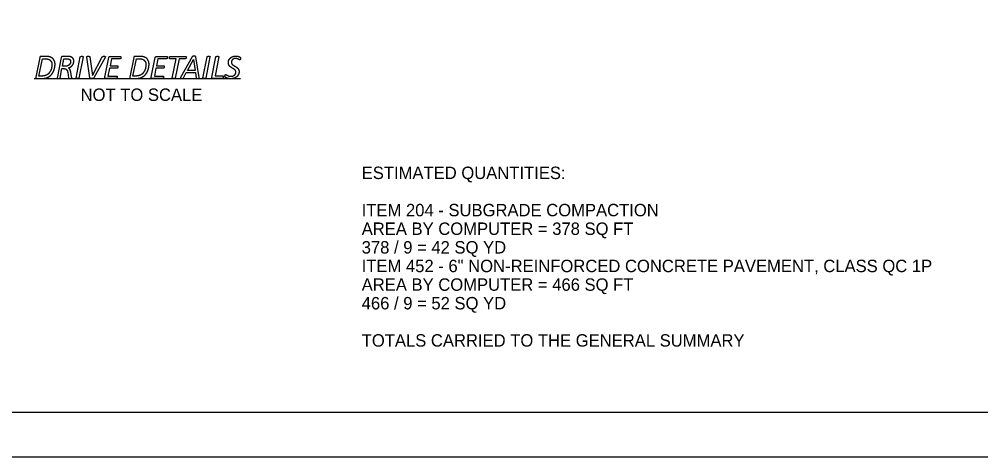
# Model space of a CAD drawing. Extents: x 0 to 3518, y -260 to 220.
# Drawn here: x 60.2 to 168.6, y -220 to -170.7 of the extents above; entities that cross this region are included whole.
import ezdxf

# ---------------------------------------------------------------- set-up
doc = ezdxf.new("R2010")
doc.units = 0
for name, color, linetype in [('DR_X_Culvert', 7, 'Continuous'), ('PF_X_Ground_Line', 7, 'Continuous'), ('SC_Scratch1', 7, 'Continuous'), ('TX_P_1', 7, 'Continuous')]:
    doc.layers.add(name, color=color, linetype=linetype)

msp = doc.modelspace()

# ---------------------------------------------------------------- linework, layer by layer
at = {"layer": 'DR_X_Culvert'}
for p, q in [((62.52, -174.98), (62.08, -177.2)), ((63.21, -174.85), (62.68, -174.85)), ((64.94, -174.98), (64.48, -177.29)), ((65.65, -174.85), (65.11, -174.85)), ((66.01, -175.42), (66.01, -175.42)), ((66.36, -175.37), (66.36, -175.37)), ((66.62, -177.29), (67.1, -174.9)), ((67.43, -174.9), (66.95, -177.29)), ((68.18, -177.28), (67.83, -174.95)), ((69.9, -174.97), (68.62, -177.28)), ((69.86, -177.2), (70.31, -174.98)), ((70.46, -174.85), (71.64, -174.85)), ((71.68, -174.91), (71.68, -174.91)), ((73.12, -174.98), (72.68, -177.2)), ((73.81, -174.85), (73.28, -174.85)), ((75.1, -177.2), (75.54, -174.98)), ((75.69, -174.85), (76.87, -174.85)), ((76.92, -174.91), (76.92, -174.91)), ((77.26, -174.85), (78.99, -174.85)), ((79.7, -174.91), (78.4, -177.22)), ((79.04, -174.92), (79.04, -174.92)), ((80.51, -177.22), (80.14, -174.91)), ((80.91, -177.29), (81.39, -174.9)), ((81.72, -174.9), (81.24, -177.29)), ((81.92, -177.2), (82.38, -174.9)), ((85.17, -175.03), (85.17, -175.03)), ((63.9, -175.77), (63.9, -175.77)), ((64.25, -175.74), (64.25, -175.74)), ((65.68, -176.68), (65.78, -177.27)), ((66.12, -177.16), (66.02, -176.61)), ((74.5, -175.77), (74.5, -175.77)), ((74.85, -175.74), (74.85, -175.74)), ((61.9, -177.34), (85.17, -177.34)), ((62.18, -177.34), (62.73, -177.34)), ((71.15, -177.34), (69.96, -177.34)), ((72.78, -177.34), (73.33, -177.34)), ((76.39, -177.34), (75.19, -177.34)), ((83.12, -177.34), (82.02, -177.34)), ((83.22, -177.12), (83.22, -177.12))]:
    msp.add_line(p, q, dxfattribs=at)
for points in [[(62.78, -177.06), (62.43, -177.06), (62.82, -175.12), (63.17, -175.12)], [(65.37, -175.96), (65.08, -175.96), (65.25, -175.12), (65.59, -175.12)], [(68.17, -174.9), (68.46, -177), (68.46, -177), (69.57, -174.9)], [(71.58, -175.12), (70.61, -175.12), (70.45, -175.9), (71.29, -175.9)], [(73.38, -177.06), (73.03, -177.06), (73.42, -175.12), (73.77, -175.12)], [(76.82, -175.12), (75.85, -175.12), (75.69, -175.9), (76.53, -175.9)], [(77.47, -177.29), (77.9, -175.13), (77.2, -175.13)], [(78.93, -175.13), (78.23, -175.13), (77.8, -177.29)], [(82.71, -174.9), (82.29, -177.05), (83.18, -177.05)], [(64.81, -177.29), (65.03, -176.23), (65.25, -176.23)], [(71.24, -176.17), (70.4, -176.17), (70.22, -177.06), (71.21, -177.06)], [(76.47, -176.17), (75.63, -176.17), (75.46, -177.06), (76.45, -177.06)], [(78.73, -177.28), (79.05, -176.68), (80.09, -176.68), (80.18, -177.29)]]:
    msp.add_lwpolyline(points, dxfattribs=at)
msp.add_lwpolyline([(79.86, -175.18), (80.05, -176.42), (79.19, -176.42), (79.86, -175.18)], close=True, dxfattribs=at)
for points in [[(62.58, -174.88), (62.53, -174.91), (62.52, -174.98)], [(62.68, -174.85), (62.62, -174.85), (62.58, -174.88)], [(63.17, -175.12), (63.38, -175.12), (63.52, -175.17)], [(63.68, -174.91), (63.49, -174.85), (63.21, -174.85)], [(63.52, -175.17), (63.65, -175.22), (63.73, -175.31)], [(63.99, -175.08), (63.87, -174.97), (63.68, -174.91)], [(63.73, -175.31), (63.82, -175.39), (63.86, -175.51)], [(63.86, -175.51), (63.9, -175.63), (63.9, -175.77)], [(64.18, -175.37), (64.12, -175.2), (63.99, -175.08)], [(64.25, -175.74), (64.25, -175.53), (64.18, -175.37)], [(65.01, -174.88), (64.96, -174.91), (64.94, -174.98)], [(65.11, -174.85), (65.05, -174.85), (65.01, -174.88)], [(65.59, -175.12), (65.7, -175.12), (65.78, -175.14)], [(65.96, -174.88), (65.82, -174.85), (65.65, -174.85)], [(65.78, -175.14), (65.86, -175.16), (65.91, -175.2)], [(65.97, -175.62), (65.93, -175.71), (65.86, -175.79)], [(65.91, -175.2), (65.96, -175.24), (65.98, -175.3)], [(66.18, -174.98), (66.09, -174.92), (65.96, -174.88)], [(66.01, -175.42), (66.01, -175.52), (65.97, -175.62)], [(65.98, -175.3), (66.01, -175.35), (66.01, -175.42)], [(66.32, -175.15), (66.27, -175.05), (66.18, -174.98)], [(66.21, -175.84), (66.29, -175.74), (66.33, -175.62)], [(66.36, -175.37), (66.36, -175.24), (66.32, -175.15)], [(66.33, -175.62), (66.36, -175.5), (66.36, -175.37)], [(67.1, -174.9), (67.1, -174.88), (67.11, -174.87)], [(67.11, -174.87), (67.12, -174.86), (67.15, -174.85)], [(67.15, -174.85), (67.17, -174.85), (67.2, -174.84)], [(67.2, -174.84), (67.23, -174.84), (67.28, -174.84)], [(67.28, -174.84), (67.32, -174.84), (67.35, -174.84)], [(67.35, -174.84), (67.38, -174.85), (67.4, -174.85)], [(67.4, -174.85), (67.42, -174.86), (67.43, -174.87)], [(67.43, -174.87), (67.43, -174.88), (67.43, -174.9)], [(67.82, -174.89), (67.83, -174.87), (67.84, -174.86)], [(67.83, -174.95), (67.82, -174.91), (67.82, -174.89)], [(67.84, -174.86), (67.86, -174.84), (67.89, -174.84)], [(67.89, -174.84), (67.93, -174.84), (67.98, -174.84)], [(67.98, -174.84), (68.04, -174.84), (68.08, -174.84)], [(68.08, -174.84), (68.11, -174.84), (68.13, -174.85)], [(68.13, -174.85), (68.15, -174.86), (68.16, -174.87)], [(68.16, -174.87), (68.16, -174.88), (68.17, -174.9)], [(69.57, -174.9), (69.58, -174.88), (69.59, -174.87)], [(69.59, -174.87), (69.6, -174.86), (69.62, -174.85)], [(69.62, -174.85), (69.65, -174.84), (69.68, -174.84)], [(69.68, -174.84), (69.72, -174.84), (69.77, -174.84)], [(69.77, -174.84), (69.83, -174.84), (69.87, -174.84)], [(69.87, -174.84), (69.9, -174.85), (69.92, -174.86)], [(69.92, -174.9), (69.92, -174.92), (69.9, -174.97)], [(69.92, -174.86), (69.93, -174.87), (69.92, -174.9)], [(70.31, -174.98), (70.32, -174.91), (70.37, -174.88)], [(70.37, -174.88), (70.42, -174.85), (70.46, -174.85)], [(71.62, -175.11), (71.6, -175.12), (71.58, -175.12)], [(71.65, -175.08), (71.63, -175.1), (71.62, -175.11)], [(71.64, -174.85), (71.68, -174.85), (71.68, -174.91)], [(71.66, -175.03), (71.66, -175.06), (71.65, -175.08)], [(71.68, -174.98), (71.67, -175.01), (71.66, -175.03)], [(71.68, -174.91), (71.68, -174.92), (71.68, -174.94)], [(71.68, -174.94), (71.68, -174.96), (71.68, -174.98)], [(73.18, -174.88), (73.13, -174.91), (73.12, -174.98)], [(73.28, -174.85), (73.22, -174.85), (73.18, -174.88)], [(73.77, -175.12), (73.98, -175.12), (74.12, -175.17)], [(74.28, -174.91), (74.09, -174.85), (73.81, -174.85)], [(74.12, -175.17), (74.25, -175.22), (74.33, -175.31)], [(74.6, -175.08), (74.47, -174.97), (74.28, -174.91)], [(74.33, -175.31), (74.42, -175.39), (74.46, -175.51)], [(74.46, -175.51), (74.5, -175.63), (74.5, -175.77)], [(74.78, -175.37), (74.72, -175.2), (74.6, -175.08)], [(74.85, -175.74), (74.85, -175.53), (74.78, -175.37)], [(75.54, -174.98), (75.56, -174.91), (75.6, -174.88)], [(75.6, -174.88), (75.65, -174.85), (75.69, -174.85)], [(76.85, -175.11), (76.84, -175.12), (76.82, -175.12)], [(76.88, -175.08), (76.87, -175.1), (76.85, -175.11)], [(76.87, -174.85), (76.92, -174.85), (76.92, -174.91)], [(76.9, -175.03), (76.89, -175.06), (76.88, -175.08)], [(76.91, -174.98), (76.9, -175.01), (76.9, -175.03)], [(76.92, -174.94), (76.91, -174.96), (76.91, -174.98)], [(76.92, -174.91), (76.92, -174.92), (76.92, -174.94)], [(77.16, -175.03), (77.16, -175.01), (77.17, -174.99)], [(77.16, -175.06), (77.16, -175.05), (77.16, -175.03)], [(77.17, -175.11), (77.16, -175.1), (77.16, -175.06)], [(77.17, -174.99), (77.17, -174.96), (77.18, -174.94)], [(77.2, -175.13), (77.18, -175.13), (77.17, -175.11)], [(77.18, -174.94), (77.19, -174.91), (77.2, -174.89)], [(77.2, -174.89), (77.21, -174.87), (77.23, -174.86)], [(77.23, -174.86), (77.24, -174.85), (77.26, -174.85)], [(78.97, -175.12), (78.95, -175.13), (78.93, -175.13)], [(79, -175.09), (78.99, -175.1), (78.97, -175.12)], [(78.99, -174.85), (79.02, -174.85), (79.03, -174.87)], [(79.02, -175.04), (79.01, -175.07), (79, -175.09)], [(79.03, -174.99), (79.02, -175.01), (79.02, -175.04)], [(79.03, -174.87), (79.04, -174.88), (79.04, -174.92)], [(79.04, -174.92), (79.04, -174.93), (79.03, -174.95)], [(79.03, -174.95), (79.03, -174.97), (79.03, -174.99)], [(79.73, -174.87), (79.71, -174.88), (79.7, -174.91)], [(79.77, -174.85), (79.74, -174.86), (79.73, -174.87)], [(79.83, -174.84), (79.79, -174.84), (79.77, -174.85)], [(79.92, -174.84), (79.87, -174.84), (79.83, -174.84)], [(80.03, -174.84), (79.99, -174.84), (79.92, -174.84)], [(80.09, -174.85), (80.07, -174.84), (80.03, -174.84)], [(80.12, -174.87), (80.12, -174.86), (80.09, -174.85)], [(80.14, -174.91), (80.13, -174.89), (80.12, -174.87)], [(81.39, -174.9), (81.39, -174.88), (81.41, -174.87)], [(81.41, -174.87), (81.42, -174.86), (81.44, -174.85)], [(81.44, -174.85), (81.46, -174.85), (81.49, -174.84)], [(81.49, -174.84), (81.52, -174.84), (81.57, -174.84)], [(81.57, -174.84), (81.62, -174.84), (81.65, -174.84)], [(81.65, -174.84), (81.68, -174.85), (81.7, -174.85)], [(81.7, -174.85), (81.71, -174.86), (81.72, -174.87)], [(81.72, -174.87), (81.73, -174.88), (81.72, -174.9)], [(82.38, -174.9), (82.39, -174.88), (82.4, -174.87)], [(82.4, -174.87), (82.41, -174.86), (82.43, -174.85)], [(82.43, -174.85), (82.45, -174.85), (82.48, -174.84)], [(82.48, -174.84), (82.52, -174.84), (82.56, -174.84)], [(82.56, -174.84), (82.61, -174.84), (82.64, -174.84)], [(82.64, -174.84), (82.67, -174.85), (82.69, -174.85)], [(82.69, -174.85), (82.71, -174.86), (82.71, -174.87)], [(82.71, -174.87), (82.72, -174.88), (82.71, -174.9)], [(83.79, -175.54), (83.79, -175.39), (83.85, -175.26)], [(83.82, -175.76), (83.79, -175.67), (83.79, -175.54)], [(83.85, -175.26), (83.91, -175.13), (84.02, -175.03)], [(84.02, -175.03), (84.13, -174.93), (84.28, -174.87)], [(84.16, -175.36), (84.13, -175.43), (84.13, -175.52)], [(84.13, -175.52), (84.13, -175.6), (84.17, -175.66)], [(84.25, -175.22), (84.19, -175.28), (84.16, -175.36)], [(84.4, -175.12), (84.31, -175.16), (84.25, -175.22)], [(84.28, -174.87), (84.44, -174.81), (84.63, -174.81)], [(84.6, -175.09), (84.49, -175.09), (84.4, -175.12)], [(84.79, -175.11), (84.71, -175.09), (84.6, -175.09)], [(84.63, -174.81), (84.72, -174.81), (84.81, -174.83)], [(84.93, -175.16), (84.87, -175.14), (84.79, -175.11)], [(84.81, -174.83), (84.89, -174.84), (84.96, -174.86)], [(85.03, -175.22), (84.99, -175.19), (84.93, -175.16)], [(84.96, -174.86), (85.02, -174.88), (85.07, -174.91)], [(85.09, -175.24), (85.06, -175.24), (85.03, -175.22)], [(85.07, -174.91), (85.12, -174.94), (85.14, -174.95)], [(85.11, -175.23), (85.1, -175.24), (85.09, -175.24)], [(85.13, -175.2), (85.12, -175.22), (85.11, -175.23)], [(85.15, -175.16), (85.14, -175.18), (85.13, -175.2)], [(85.14, -174.95), (85.15, -174.97), (85.16, -174.99)], [(85.16, -175.11), (85.16, -175.13), (85.15, -175.16)], [(85.16, -174.99), (85.17, -175.01), (85.17, -175.03)], [(85.17, -175.07), (85.17, -175.09), (85.16, -175.11)], [(85.17, -175.03), (85.17, -175.05), (85.17, -175.07)], [(63.65, -176.62), (63.57, -176.75), (63.45, -176.85)], [(63.79, -176.35), (63.74, -176.49), (63.65, -176.62)], [(63.87, -176.06), (63.85, -176.21), (63.79, -176.35)], [(63.9, -175.77), (63.9, -175.91), (63.87, -176.06)], [(63.93, -176.79), (64.02, -176.67), (64.08, -176.54)], [(64.08, -176.54), (64.14, -176.41), (64.17, -176.28)], [(64.17, -176.28), (64.21, -176.14), (64.23, -176)], [(64.23, -176), (64.25, -175.87), (64.25, -175.74)], [(65.25, -176.23), (65.36, -176.23), (65.44, -176.26)], [(65.66, -175.91), (65.54, -175.96), (65.37, -175.96)], [(65.44, -176.26), (65.51, -176.29), (65.56, -176.35)], [(65.56, -176.35), (65.61, -176.41), (65.64, -176.5)], [(65.64, -176.5), (65.67, -176.58), (65.68, -176.68)], [(65.86, -175.79), (65.78, -175.87), (65.66, -175.91)], [(65.76, -176.14), (65.91, -176.1), (66.02, -176.02)], [(65.92, -176.3), (65.86, -176.18), (65.76, -176.14)], [(66.02, -176.61), (65.98, -176.41), (65.92, -176.3)], [(66.02, -176.02), (66.14, -175.94), (66.21, -175.84)], [(71.27, -176.16), (71.26, -176.17), (71.24, -176.17)], [(71.3, -176.13), (71.29, -176.15), (71.27, -176.16)], [(71.29, -175.9), (71.31, -175.9), (71.33, -175.92)], [(71.32, -176.09), (71.31, -176.11), (71.3, -176.13)], [(71.33, -176.04), (71.32, -176.06), (71.32, -176.09)], [(71.33, -175.92), (71.34, -175.94), (71.34, -175.97)], [(71.34, -175.97), (71.34, -175.98), (71.33, -176)], [(71.33, -176), (71.33, -176.02), (71.33, -176.04)], [(74.25, -176.62), (74.17, -176.75), (74.05, -176.85)], [(74.39, -176.35), (74.34, -176.49), (74.25, -176.62)], [(74.47, -176.06), (74.45, -176.21), (74.39, -176.35)], [(74.5, -175.77), (74.5, -175.91), (74.47, -176.06)], [(74.53, -176.79), (74.62, -176.67), (74.68, -176.54)], [(74.68, -176.54), (74.74, -176.41), (74.77, -176.28)], [(74.77, -176.28), (74.81, -176.14), (74.83, -176)], [(74.83, -176), (74.85, -175.87), (74.85, -175.74)], [(76.51, -176.16), (76.49, -176.17), (76.47, -176.17)], [(76.53, -176.13), (76.52, -176.15), (76.51, -176.16)], [(76.53, -175.9), (76.55, -175.9), (76.56, -175.92)], [(76.55, -176.09), (76.54, -176.11), (76.53, -176.13)], [(76.56, -176.04), (76.56, -176.06), (76.55, -176.09)], [(76.56, -175.92), (76.57, -175.94), (76.57, -175.97)], [(76.57, -176), (76.57, -176.02), (76.56, -176.04)], [(76.57, -175.97), (76.57, -175.98), (76.57, -176)], [(83.92, -175.93), (83.86, -175.86), (83.82, -175.76)], [(84.06, -176.05), (83.98, -176), (83.92, -175.93)], [(84.21, -176.16), (84.13, -176.11), (84.06, -176.05)], [(84.17, -175.66), (84.21, -175.73), (84.27, -175.78)], [(84.37, -176.25), (84.29, -176.21), (84.21, -176.16)], [(84.27, -175.78), (84.33, -175.83), (84.4, -175.88)], [(84.51, -176.35), (84.45, -176.29), (84.37, -176.25)], [(84.4, -175.88), (84.48, -175.92), (84.56, -175.97)], [(84.61, -176.46), (84.57, -176.4), (84.51, -176.35)], [(84.56, -175.97), (84.64, -176.02), (84.72, -176.08)], [(84.6, -176.8), (84.64, -176.71), (84.64, -176.61)], [(84.64, -176.61), (84.64, -176.53), (84.61, -176.46)], [(84.72, -176.08), (84.8, -176.13), (84.86, -176.2)], [(84.86, -176.2), (84.92, -176.28), (84.96, -176.37)], [(85, -176.58), (85, -176.75), (84.93, -176.89)], [(84.96, -176.37), (85, -176.46), (85, -176.58)], [(62.08, -177.2), (62.07, -177.24), (62.07, -177.27)], [(62.07, -177.27), (62.08, -177.29), (62.09, -177.31)], [(62.09, -177.31), (62.11, -177.32), (62.13, -177.33)], [(62.13, -177.33), (62.15, -177.34), (62.18, -177.34)], [(62.73, -177.34), (62.98, -177.34), (63.16, -177.3)], [(63.17, -177), (63.01, -177.06), (62.78, -177.06)], [(63.16, -177.3), (63.33, -177.26), (63.48, -177.18)], [(63.45, -176.85), (63.33, -176.95), (63.17, -177)], [(63.48, -177.18), (63.62, -177.11), (63.73, -177.01)], [(63.73, -177.01), (63.85, -176.91), (63.93, -176.79)], [(64.48, -177.29), (64.48, -177.3), (64.49, -177.32)], [(64.49, -177.32), (64.49, -177.33), (64.51, -177.33)], [(64.51, -177.33), (64.53, -177.34), (64.56, -177.34)], [(64.56, -177.34), (64.59, -177.35), (64.63, -177.35)], [(64.63, -177.35), (64.68, -177.35), (64.71, -177.34)], [(64.71, -177.34), (64.75, -177.34), (64.77, -177.33)], [(64.77, -177.33), (64.79, -177.33), (64.8, -177.31)], [(64.8, -177.31), (64.81, -177.3), (64.81, -177.29)], [(65.78, -177.27), (65.79, -177.29), (65.79, -177.31)], [(65.79, -177.31), (65.8, -177.32), (65.82, -177.33)], [(65.82, -177.33), (65.83, -177.34), (65.86, -177.34)], [(65.86, -177.34), (65.9, -177.35), (65.95, -177.35)], [(65.95, -177.35), (66, -177.35), (66.04, -177.34)], [(66.04, -177.34), (66.07, -177.34), (66.09, -177.33)], [(66.09, -177.33), (66.12, -177.33), (66.13, -177.31)], [(66.13, -177.23), (66.13, -177.19), (66.12, -177.16)], [(66.13, -177.28), (66.13, -177.26), (66.13, -177.23)], [(66.13, -177.31), (66.13, -177.3), (66.13, -177.28)], [(66.62, -177.31), (66.62, -177.3), (66.62, -177.29)], [(66.65, -177.33), (66.63, -177.33), (66.62, -177.31)], [(66.69, -177.34), (66.66, -177.34), (66.65, -177.33)], [(66.77, -177.35), (66.72, -177.35), (66.69, -177.34)], [(66.85, -177.34), (66.82, -177.35), (66.77, -177.35)], [(66.91, -177.33), (66.89, -177.34), (66.85, -177.34)], [(66.94, -177.31), (66.93, -177.33), (66.91, -177.33)], [(66.95, -177.29), (66.95, -177.3), (66.94, -177.31)], [(68.19, -177.31), (68.18, -177.3), (68.18, -177.28)], [(68.23, -177.33), (68.2, -177.33), (68.19, -177.31)], [(68.29, -177.35), (68.25, -177.34), (68.23, -177.33)], [(68.39, -177.35), (68.33, -177.35), (68.29, -177.35)], [(68.49, -177.35), (68.45, -177.35), (68.39, -177.35)], [(68.55, -177.33), (68.53, -177.34), (68.49, -177.35)], [(68.59, -177.31), (68.58, -177.33), (68.55, -177.33)], [(68.62, -177.28), (68.61, -177.3), (68.59, -177.31)], [(69.86, -177.26), (69.86, -177.24), (69.86, -177.2)], [(69.88, -177.31), (69.87, -177.29), (69.86, -177.26)], [(69.92, -177.33), (69.9, -177.32), (69.88, -177.31)], [(69.96, -177.34), (69.94, -177.34), (69.92, -177.33)], [(71.19, -177.32), (71.17, -177.34), (71.15, -177.34)], [(71.22, -177.29), (71.21, -177.31), (71.19, -177.32)], [(71.21, -177.06), (71.23, -177.06), (71.24, -177.08)], [(71.23, -177.25), (71.23, -177.27), (71.22, -177.29)], [(71.25, -177.2), (71.24, -177.22), (71.23, -177.25)], [(71.24, -177.08), (71.25, -177.09), (71.25, -177.13)], [(71.25, -177.13), (71.25, -177.14), (71.25, -177.16)], [(71.25, -177.16), (71.25, -177.18), (71.25, -177.2)], [(72.68, -177.2), (72.67, -177.24), (72.67, -177.27)], [(72.67, -177.27), (72.68, -177.29), (72.69, -177.31)], [(72.69, -177.31), (72.71, -177.32), (72.73, -177.33)], [(72.73, -177.33), (72.75, -177.34), (72.78, -177.34)], [(73.33, -177.34), (73.58, -177.34), (73.76, -177.3)], [(73.77, -177), (73.61, -177.06), (73.38, -177.06)], [(73.76, -177.3), (73.93, -177.26), (74.08, -177.18)], [(74.05, -176.85), (73.93, -176.95), (73.77, -177)], [(74.08, -177.18), (74.22, -177.11), (74.33, -177.01)], [(74.33, -177.01), (74.45, -176.91), (74.53, -176.79)], [(75.1, -177.26), (75.09, -177.24), (75.1, -177.2)], [(75.12, -177.31), (75.1, -177.29), (75.1, -177.26)], [(75.15, -177.33), (75.13, -177.32), (75.12, -177.31)], [(75.19, -177.34), (75.17, -177.34), (75.15, -177.33)], [(76.42, -177.32), (76.41, -177.34), (76.39, -177.34)], [(76.45, -177.29), (76.44, -177.31), (76.42, -177.32)], [(76.45, -177.06), (76.46, -177.06), (76.48, -177.08)], [(76.47, -177.25), (76.46, -177.27), (76.45, -177.29)], [(76.48, -177.2), (76.48, -177.22), (76.47, -177.25)], [(76.48, -177.08), (76.49, -177.09), (76.49, -177.13)], [(76.49, -177.16), (76.49, -177.18), (76.48, -177.2)], [(76.49, -177.13), (76.49, -177.14), (76.49, -177.16)], [(77.47, -177.31), (77.46, -177.3), (77.47, -177.29)], [(77.49, -177.33), (77.48, -177.33), (77.47, -177.31)], [(77.54, -177.34), (77.51, -177.34), (77.49, -177.33)], [(77.62, -177.35), (77.57, -177.35), (77.54, -177.34)], [(77.7, -177.34), (77.67, -177.35), (77.62, -177.35)], [(77.75, -177.33), (77.73, -177.34), (77.7, -177.34)], [(77.78, -177.31), (77.77, -177.33), (77.75, -177.33)], [(77.8, -177.29), (77.8, -177.3), (77.78, -177.31)], [(78.38, -177.29), (78.37, -177.31), (78.38, -177.33)], [(78.4, -177.22), (78.38, -177.26), (78.38, -177.29)], [(78.38, -177.33), (78.4, -177.34), (78.43, -177.34)], [(78.43, -177.34), (78.47, -177.35), (78.52, -177.35)], [(78.52, -177.35), (78.57, -177.35), (78.61, -177.35)], [(78.61, -177.35), (78.65, -177.34), (78.67, -177.33)], [(78.67, -177.33), (78.69, -177.33), (78.7, -177.31)], [(78.7, -177.31), (78.72, -177.3), (78.73, -177.28)], [(80.18, -177.29), (80.18, -177.31), (80.19, -177.32)], [(80.19, -177.32), (80.2, -177.33), (80.21, -177.34)], [(80.21, -177.34), (80.23, -177.34), (80.26, -177.35)], [(80.26, -177.35), (80.29, -177.35), (80.33, -177.35)], [(80.33, -177.35), (80.4, -177.35), (80.44, -177.34)], [(80.44, -177.34), (80.48, -177.34), (80.49, -177.33)], [(80.49, -177.33), (80.51, -177.31), (80.51, -177.29)], [(80.51, -177.29), (80.52, -177.26), (80.51, -177.22)], [(80.92, -177.31), (80.91, -177.3), (80.91, -177.29)], [(80.94, -177.33), (80.92, -177.33), (80.92, -177.31)], [(80.99, -177.34), (80.96, -177.34), (80.94, -177.33)], [(81.07, -177.35), (81.02, -177.35), (80.99, -177.34)], [(81.15, -177.34), (81.11, -177.35), (81.07, -177.35)], [(81.2, -177.33), (81.18, -177.34), (81.15, -177.34)], [(81.23, -177.31), (81.22, -177.33), (81.2, -177.33)], [(81.24, -177.29), (81.24, -177.3), (81.23, -177.31)], [(81.92, -177.26), (81.91, -177.24), (81.92, -177.2)], [(81.94, -177.31), (81.93, -177.29), (81.92, -177.26)], [(81.98, -177.33), (81.96, -177.32), (81.94, -177.31)], [(82.02, -177.34), (82, -177.34), (81.98, -177.33)], [(83.16, -177.32), (83.14, -177.34), (83.12, -177.34)], [(83.18, -177.29), (83.17, -177.31), (83.16, -177.32)], [(83.18, -177.05), (83.2, -177.05), (83.21, -177.07)], [(83.2, -177.24), (83.2, -177.27), (83.18, -177.29)], [(83.21, -177.19), (83.21, -177.22), (83.2, -177.24)], [(83.21, -177.07), (83.22, -177.08), (83.22, -177.12)], [(83.22, -177.15), (83.22, -177.17), (83.21, -177.19)], [(83.22, -177.12), (83.22, -177.12), (83.22, -177.15)], [(83.41, -177.08), (83.41, -177.06), (83.42, -177.03)], [(83.41, -177.11), (83.41, -177.1), (83.41, -177.08)], [(83.43, -177.19), (83.41, -177.16), (83.41, -177.11)], [(83.42, -177.03), (83.42, -177.01), (83.43, -176.98)], [(83.43, -176.98), (83.44, -176.96), (83.45, -176.94)], [(83.51, -177.24), (83.46, -177.21), (83.43, -177.19)], [(83.45, -176.94), (83.46, -176.92), (83.47, -176.91)], [(83.47, -176.91), (83.48, -176.9), (83.5, -176.9)], [(83.5, -176.9), (83.53, -176.9), (83.58, -176.93)], [(83.65, -177.3), (83.57, -177.27), (83.51, -177.24)], [(83.58, -176.93), (83.62, -176.96), (83.69, -176.99)], [(83.83, -177.35), (83.73, -177.33), (83.65, -177.3)], [(83.69, -176.99), (83.76, -177.03), (83.86, -177.06)], [(84.05, -177.37), (83.93, -177.37), (83.83, -177.35)], [(83.86, -177.06), (83.95, -177.09), (84.08, -177.09)], [(84.44, -177.31), (84.26, -177.37), (84.05, -177.37)], [(84.08, -177.09), (84.21, -177.09), (84.32, -177.05)], [(84.32, -177.05), (84.42, -177.01), (84.49, -176.95)], [(84.74, -177.14), (84.61, -177.25), (84.44, -177.31)], [(84.49, -176.95), (84.57, -176.89), (84.6, -176.8)], [(84.93, -176.89), (84.86, -177.04), (84.74, -177.14)]]:
    msp.add_open_spline(points, degree=2, dxfattribs=at)
at = {"layer": 'PF_X_Ground_Line'}
msp.add_lwpolyline([(15, -5), (335, -5), (335, -215), (15, -215)], close=True, dxfattribs=at)
at = {"layer": 'SC_Scratch1'}
msp.add_lwpolyline([(0, -220), (340, -220), (340, 0), (0, 0)], close=True, dxfattribs=at)

# ---------------------------------------------------------------- texts
at = {"layer": 'TX_P_1'}
for s, p in [('NOT TO SCALE', (67.13, -179.87)), ('ESTIMATED QUANTITIES:', (98.83, -188.68)), ('ITEM 204 - SUBGRADE COMPACTION', (98.83, -192.88)), ('AREA BY COMPUTER = 378 SQ FT', (98.83, -194.98)), ('378 / 9 = 42 SQ YD', (98.83, -197.08)), ('ITEM 452 - 6" NON-REINFORCED CONCRETE PAVEMENT, CLASS QC 1P', (98.83, -199.18)), ('AREA BY COMPUTER = 466 SQ FT', (98.83, -201.28)), ('466 / 9 = 52 SQ YD', (98.83, -203.38)), ('TOTALS CARRIED TO THE GENERAL SUMMARY', (98.83, -207.58))]:
    msp.add_text(s, height=1.4, dxfattribs=at).set_placement(p)

doc.saveas('drawing.dxf')
